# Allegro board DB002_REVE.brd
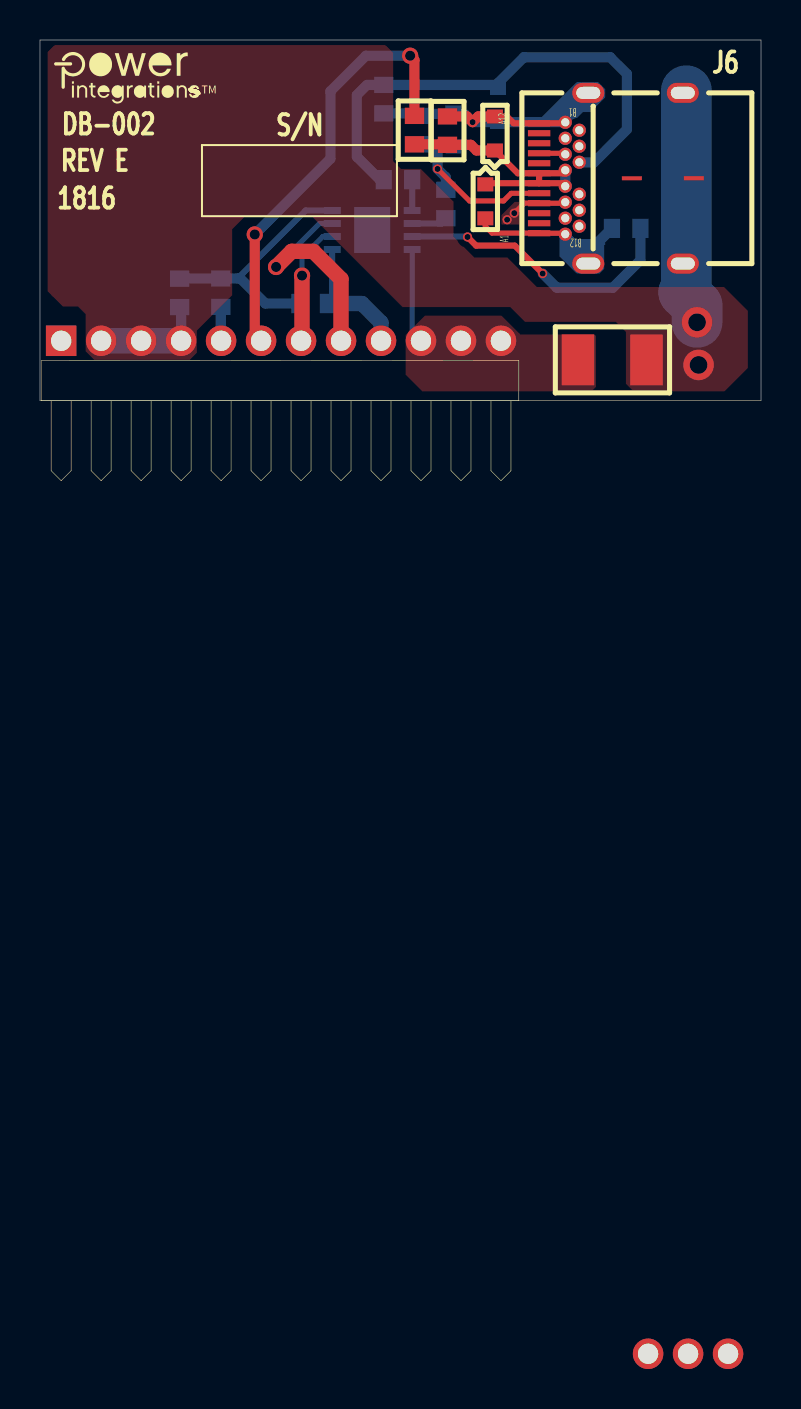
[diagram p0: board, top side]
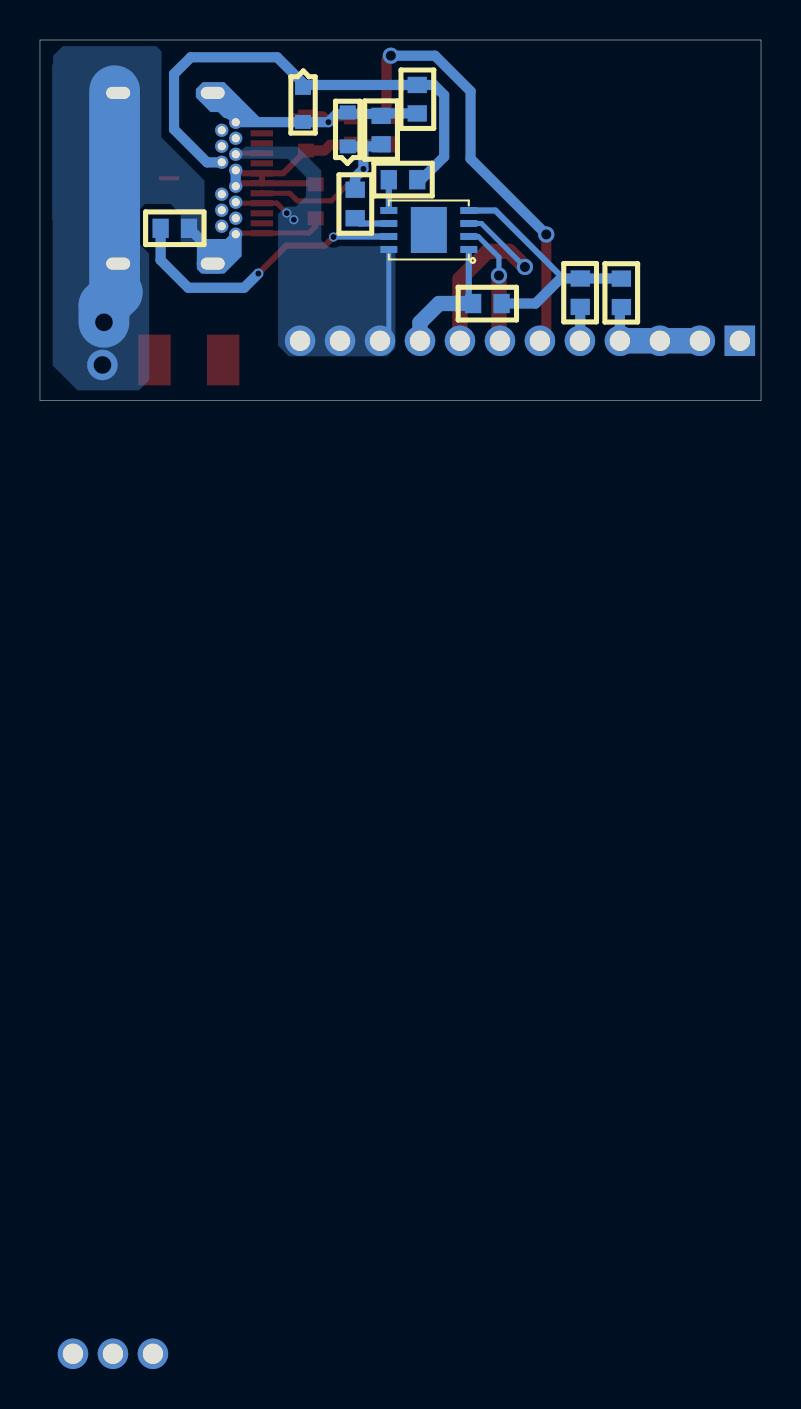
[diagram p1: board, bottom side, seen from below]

Outline 36.07 x 18.03 mm; copper layers: TOP, BOTTOM. Coordinates in mm from the lower left corner of the outline.
Outline path: 0,18.03 0,0 36.07,0 36.07,18.03 0,18.03

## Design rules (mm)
constraint set DEFAULT: min track width 0.508

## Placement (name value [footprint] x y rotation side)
C14  10 uF  [PISMC1210]  26.91 2.03 0 top
C15  560 pF  [PISMC0603]  17.2 14.36 90 bottom
C16  560 pF  [PISMC0603]  19 14.24 270 bottom
C17  2.2 uF  [PISMC0603]  14.4 4.85 180 bottom
D9  DZ2J240M0L  [PI_SM_D_SSMINI2P]  22.91 15.64 270 bottom
D10  DZ2J240M0L  [PI_SM_D_SSMINI2P]  20.68 12.71 90 bottom
D11  DZ2J240M0L  [PI_SM_D_SSMINI2P]  22.28 10.81 270 top
D12  DZ2J240M0L  [PI_SM_D_SSMINI2P]  22.76 12.51 90 top
J5  CON15  [PI_UNSHROUD_2MM_15PRA]  1.06 2.99 0 bottom
J6  CON24_USB_C  [PI_CONN_USBC_WURTH]  26.98 11.12 90 top
NOREF  -  []  -250.22 -170.79 0 top
NOREF#2  -  []  0.15 17.32 0 top
NOREF#3  -  []  -172.4 28.22 0 top
NOREF#4  -  []  -0.03 -0.03 90 top
NOREF#5  -  []  0 18.01 0 top
R14  0.0  [PISMR0603]  9.04 6.1 270 bottom
R15  0.0  [PISMR0603]  6.99 6.1 270 bottom
R17  22  [PISMR0603]  20.3 9.12 90 bottom
R18  22  [PISMR0603]  17.2 11.04 0 bottom
R19  63.4 k  [PISMR0603]  18.73 12.81 90 top
R20  100 k  [PISMR0603]  20.38 12.79 90 top
RT4  100 k  [PISMR0603]  28.61 8.61 0 bottom
U4  VP302  [PI_SM_DFN-8]  14.62 7.55 90 bottom

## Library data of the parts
C14-C16 = CAP NP: room: 3
C17 = CAP NP
D9-D12 = DIODE_ZENER: room: 3
J5 = CON15: room: 3
J6 = CON24_USB: room: 3
R14 R15 R19 R20 = R
R17 R18 = R: room: 3
RT4 = THERMISTOR: room: 3
U4 = VP302: room: 3

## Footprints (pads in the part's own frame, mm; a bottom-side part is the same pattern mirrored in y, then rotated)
PI_CONN_USBC_WURTH
  oval 1.001x1.6 hole 0.599x1.199: (-4.27,-0.45) (-4.27,-5.179) (4.27,-0.45) (4.27,-5.179)
  round 0.66 hole 0.406: (-1.999,0.701) (1.999,0.701) B1(2.799,0.701) B2(2.4,0) B3(1.6,0) B4(1.199,0.701) B5(0.8,0) B6(0.399,0.701) B7(-0.399,0.701) B8(-0.8,0) B9(-1.199,0.701) B10(-1.6,0) B11(-2.4,0) B12(-2.799,0.701)
  rect 0.305x1.118 smd: A1(-2.751,2.009) A2(-2.25,2.009) A3(-1.75,2.009) A4(-1.25,2.009) A5(-0.749,2.009) A6(-0.249,2.009) A7(0.249,2.009) A8(0.749,2.009) A9(1.25,2.009) A10(1.75,2.009) A11(2.25,2.009) A12(2.751,2.009)
PI_SM_D_SSMINI2P
  rect 0.699x0.8 smd: 1(0,0) 2(1.699,0)
PI_SM_DFN-8
  rect 0.35x0.85 smd: 1(0,0) 2(0.65,0) 3(1.3,0) 4(1.95,0) 5(1.95,4) 6(1.3,4) 7(0.65,4) 8(0,4)
  rect 2.3x1.8 smd: 9(0.975,2)
PI_UNSHROUD_2MM_15PRA
  rect 1.524x1.524 hole 1.016: 1(0,0)
  round 1.524 hole 1.016: 2(2,0) 3(4,0) 4(6,0) 5(8,0) 6(10,0) 7(12,0) 8(14,0) 9(16,0) 10(18,0) 11(20,0) 12(22,0) 13(29.359,50.673) 14(31.359,50.673) 15(33.359,50.673)
PISMC0603
  rect 0.813x0.965 smd: 1(0,0) 2(1.422,0)
PISMC1210
  rect 1.626x2.54 smd: 1(0,0) 2(3.429,0)
PISMR0603
  rect 0.813x0.965 smd: 1(0,0) 2(1.422,0)

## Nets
GND: C14.2 C15.1 C16.1 D9.2 D10.2 D11.2 D12.2 J5.2 J5.3 J5.4 J6.A1 J6.A12 J6.B1 J6.B12 R15.2 R20.2 RT4.1
GND_SIGNAL: J5.5 R14.2
VBUS_IN: J5.1
VBUS_OUT: C14.1 J5.10 J5.11 J5.12 J6.A4 J6.A9 J6.B4 J6.B9(VBUS4) U4.8
BPS: J5.6 R19.2
D: D11.1 D12.1 J6.A6 J6.A7 J6.B6 J6.B7 R19.1 R20.1
SCL: J5.7 U4.2
SDA: J5.8 U4.3
UVCC: C17.1 J5.9 U4.1(VCC)
N12100170: C15.2 D9.1 J6.B5 R18.1
N12100174: C16.2 D10.1 J6.A5 R17.2
N12100230: RT4.2 U4.7
N12102267: C17.2 R14.1 R15.1 U4.4
N12102285: R17.1 U4.6
N12102289: R18.2 U4.5

Pads without a net: J5 13 14 15; J6 A2 A3 A8 A10 A11 B2 B3 B8 B10 B11; U4 9

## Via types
v1: diameter 0.813, hole 0.508, TOP to BOTTOM, 4 vias
v2: diameter 0.457, hole 0.305, TOP to BOTTOM, 6 vias
v3: diameter 1.524, hole 0.889, TOP to BOTTOM, 2 vias

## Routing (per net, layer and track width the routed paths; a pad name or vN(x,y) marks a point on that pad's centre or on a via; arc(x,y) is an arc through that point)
GND: length 40.9
  TOP w0.254: D11.2 22.28,8.71 22.61,8.37 24.97,8.37 24.97,8.37 J6.A1 26.23,8.37 J6.B12
  TOP w0.305: D12.2 23.36,14.21 23.7,13.87 J6.A12 26.23,13.87
  TOP w0.381: 26.23,13.87 J6.B1
  TOP w0.508: R20.2 21.35,14.21 v2(21.64,13.92) 21.92,14.21 D12.2
  BOTTOM w0.508: 26.27,13.92 J6.B1 ; 26.27,13.92 22.9,13.92 ; 26.27,13.92 26.27,13.92 ; 22.9,13.92 v2(21.64,13.92) 21.23,14.33 20.75,14.33 D10.2 20.6,14.33 19.09,14.33 C16.1 18.88,14.36 C15.1 ; 22.9,13.92 D9.2 ; J6.B12 26.28,8.22 26.72,7.77 27.77,7.77 RT4.1 ; R15.2 7.06,4.6 7.06,2.99 J5.4
  BOTTOM w1.27: 3.06,2.99 J5.2 J5.3 J5.4
  BOTTOM w2.54: 32.33,15.49 32.33,5.54 32.21,5.41 32.87,4.75 v3(32.87,3.91)
  vias: v3(32.94,1.78)
GND_SIGNAL: length 1.7
  BOTTOM w0.508: J5.5 9.04,3 R14.2
VBUS_OUT: length 8.9
  TOP w0.254: J6.A4 26.23,9.87 J6.B9 ; v2(23.72,9.37) 24.23,9.88 24.97,9.88 ; J6.B4 26.23,12.37 J6.A9
  BOTTOM w0.254: J5.10 18.62,3.43 U4.8
  vias: v2(23.37,9.04)
BPS: length 22
  TOP w0.508: v1(10.74,8.31) 10.74,3.3 J5.6 ; R19.2 18.73,17.03 v1(18.52,17.25)
  BOTTOM w0.508: v1(18.52,17.25) 16.31,17.25 14.53,15.47 14.53,12.09 v1(10.74,8.31)
D: length 13.6
  TOP w0.305: J6.A6 22.33,10.87 D11.1 ; J6.A6 26.13,10.87 J6.B7 ; J6.A6 J6.A7 ; J6.B6 26.13,11.37 J6.A7 ; D12.1 23.9,11.37 J6.A7
  TOP w0.508: R19.1 20.36,12.81 R20.1 21.55,12.79 21.83,12.51 D12.1
  BOTTOM w0.203: J6.B6 26.28,11.52 26.27,11.52
  BOTTOM w0.508: J6.B6 J6.B7
SCL: length 6.1
  TOP w0.762: J5.7 13.11,3.04 v1(13.11,6.25)
  BOTTOM w0.254: U4.2 14.15,8.2 13.11,7.17 v1(13.11,6.25)
SDA: length 10.9
  TOP w0.762: v1(11.81,6.68) 12.59,7.46 13.67,7.46 15.06,6.07 J5.8
  BOTTOM w0.254: 15.06,2.99 J5.8 ; U4.3 13.99,8.85 v1(11.81,6.68)
UVCC: length 6.8
  BOTTOM w0.305: C17.1 14.4,4.93 14.62,5.14 U4.1
  BOTTOM w0.762: C17.1 16.1,4.85 17.06,3.9 J5.9
N12100170: length 25.7
  BOTTOM w0.508: J6.B5 26.98,11.91 27.71,11.91 29.36,13.56 29.36,16.33 28.52,17.17 24.21,17.17 22.91,15.88 D9.1 22.76,15.78 C15.2 16.36,15.78 15.85,15.28 15.85,12.19 17,11.04 R18.1
N12100174: length 10
  TOP w0.254: J6.A5 24.97,10.37 24.97,10.38 24.95,10.36 23.57,10.36 23.19,9.98 21.49,9.98 v2(19.89,11.58)
  BOTTOM w0.508: C16.2 19.1,12.71 19.89,12.71 ; R17.2 20.3,11.17 v2(19.89,11.58) 19.89,12.71 ; 19.89,12.71 D10.1
N12100230: length 14.6
  TOP w0.305: v2(25.15,6.35) 23.75,7.75 21.82,7.75 v2(21.39,8.18)
  BOTTOM w0.305: U4.7 21.36,8.2 v2(21.39,8.18)
  BOTTOM w0.508: v2(25.15,6.35) 25.86,5.64 28.65,5.64 30.03,7.02 RT4.2
N12102267: length 12.7
  BOTTOM w0.305: U4.4 13.29,9.5 9.89,6.1
  BOTTOM w0.508: R15.1 6.99,6.1 R14.1 10.03,6.1 11.28,4.85 C17.2
N12102285: length 1.8
  BOTTOM w0.305: R17.1 20.3,9.07 20.09,8.85 U4.6
N12102289: length 1.5
  BOTTOM w0.305: U4.5 R18.2

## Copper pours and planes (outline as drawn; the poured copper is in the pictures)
GND on BOTTOM (solid shape): 26.59,8.41 26.59,8.26 26.77,8.08 28.04,8.08 28.3,7.82 28.22,7.75 28.22,6.58 27.99,6.35 26.85,6.35 25.98,7.21 25.98,8.48 26.01,8.51 26.49,8.51
GND on BOTTOM (solid shape): 28.27,15.57 28.27,15.16 27.53,14.43 27.15,14.43 26.87,14.14 26.85,14.14 26.57,14 26.38,13.74 26.19,13.75 26,13.69 25.02,13.69 24.99,13.72 24.99,14.07 26.85,15.93 27.91,15.93
GND on TOP: 7.85,3.51 7.85,2.39 7.49,2.03 2.72,2.03 2.29,2.46 2.29,4.32 1.91,4.7 1.14,4.7 0.38,5.46 0.38,17.42 0.74,17.78 17.27,17.78 17.67,17.39 17.67,11.98 18.06,11.58 19.02,11.58 19.04,11.6 20.69,9.94 20.69,8.19 21.72,7.16 23.37,7.16 24.85,5.68 34.23,5.68 35.41,4.5 35.41,1.63 34.24,0.46 31.11,0.46 31.09,0.48 29.67,0.48 29.31,0.84 29.31,3.43 28.8,3.94 24.26,3.94 23.52,4.67 18.14,4.67 13.61,9.19 10.24,9.19 9.61,8.57 9.61,5.27
GND on BOTTOM: 27.71,7.75 27.71,8.08 27.84,8.2 27.84,11 30,13.16 30,16.13 29.98,16.14 29.98,17.46 30.25,17.73 34.92,17.73 35.41,17.25 35.41,16.84 35.46,16.79 35.46,9.04 35.43,9.02 35.43,1.75 34.19,0.51 31.11,0.51 30.61,1.02 30.61,7.34 31.06,7.8 31.06,9.58 30.81,9.83 29.54,9.83 29.03,9.32 29.03,7.82 28.96,7.75
VBUS_OUT on TOP: 25.53,10.01 23.83,10.01 23.09,9.27 23.09,8.76 23.19,8.66 24.03,8.66 24.08,8.71 24.08,9.5 24.31,9.73 25.5,9.73 25.53,9.75
VBUS_OUT on TOP: 23.09,4.24 23.94,3.39 23.95,3.39 24.04,3.3 27.74,3.3 27.81,3.23 27.81,0.69 27.58,0.46 19.13,0.46 18.29,1.3 18.29,3.28 19.25,4.24
VBUS_OUT on BOTTOM: 22,8.03 22,11.51 23.19,12.7 25.78,12.7 25.9,12.59 26.38,12.59 26.54,12.42 26.54,12.19 26.44,12.09 23.67,12.09 22.76,11.18 22.76,10.21 23.27,9.7 23.77,9.7 24.16,9.32 24.16,2.74 23.62,2.21 18.69,2.21 18.29,2.62 18.29,7.47 18.54,7.72 21.69,7.72

Small or netless copper shapes (teardrops, artwork), in the pictures only: 2 on TOP

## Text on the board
Ref Des/Silkscreen Top: 1816 | REV E | DB-002 | S/N
User.7: PLESE DELETE THESE PINS | SLOTS | 14.  FAB HOUSE LOGO,DATE CODE TO BE IN SILK SCREEN ONLY.DO NOT USE COPPER. | 13.  MATERIAL FR4 COPPER 2oz THICKNESS 0.062"
User.9: FIGURE | FINISHED_SIZE | 12.0 | 16.0 | 20.0 | 35.0 | 40.0 | 47.201x23.598 | DRILL CHART: TOP to BOTTOM | ALL UNITS ARE IN MILS | TOLERANCE_DRILL | +3.0/-3.0 | +0.0/-0.0 | PLATED | QTY | 6 | 14 | 4 | 2 | 15
